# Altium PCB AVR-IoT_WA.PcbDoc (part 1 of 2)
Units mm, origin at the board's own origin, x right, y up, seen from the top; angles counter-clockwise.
Board outline 63.5 x 25.4 mm, 4 copper layers (Top-Layer, Ground Plane, Power Plane, Bottom Layer), stack 1.594 mm thick; 81 components, 91 nets, 345 pads, 206 vias.
Unrouted connection lines stored in the file: 10.
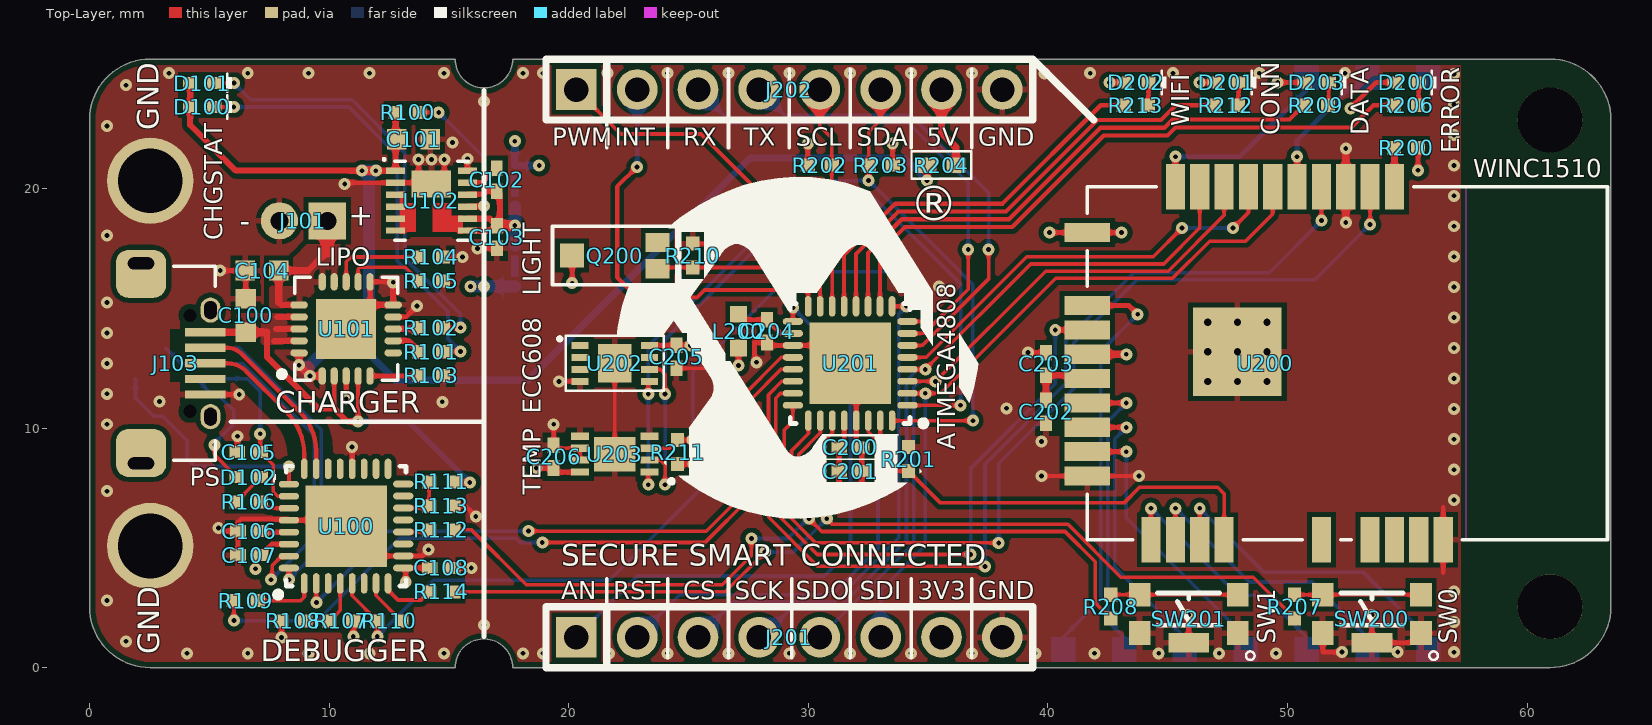
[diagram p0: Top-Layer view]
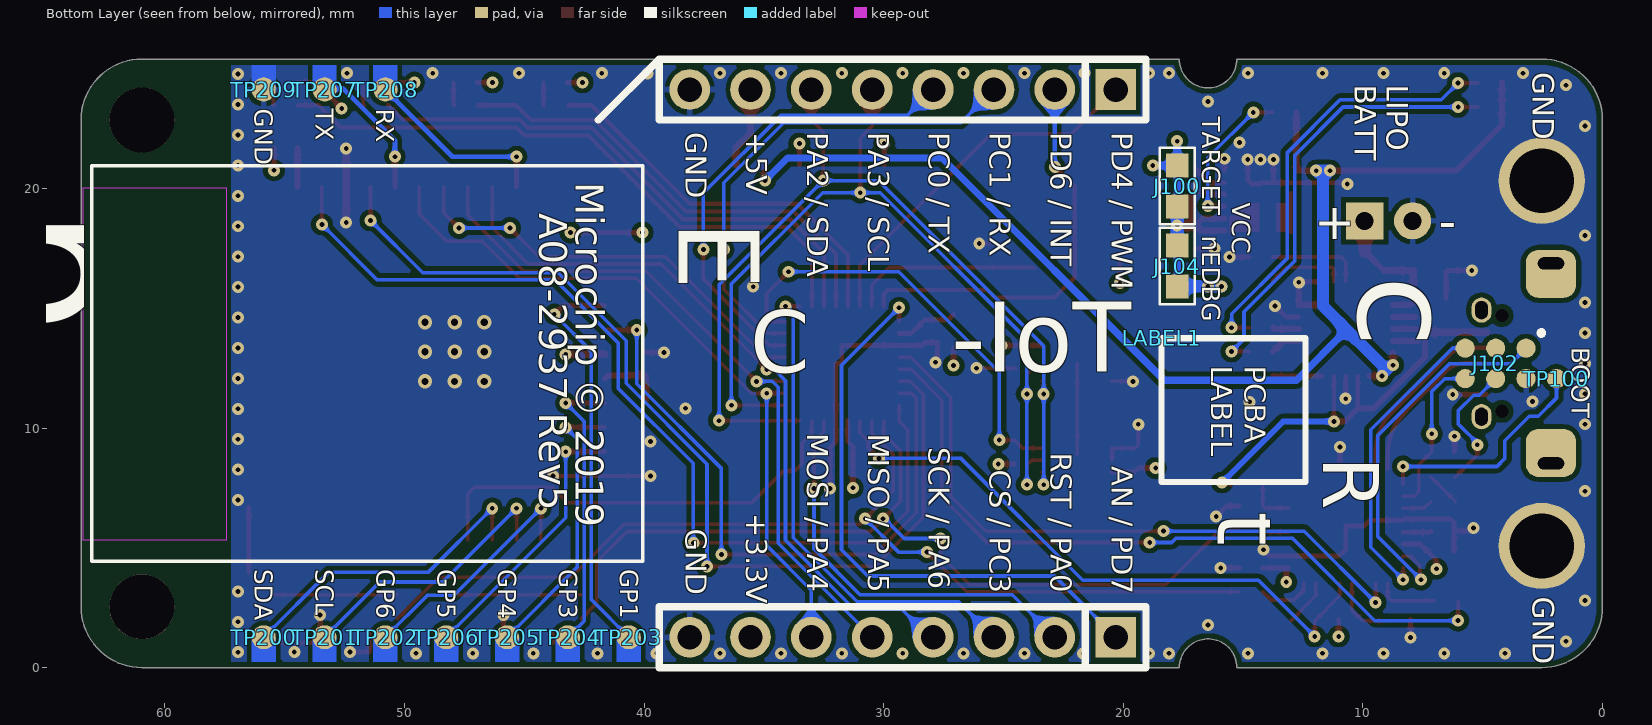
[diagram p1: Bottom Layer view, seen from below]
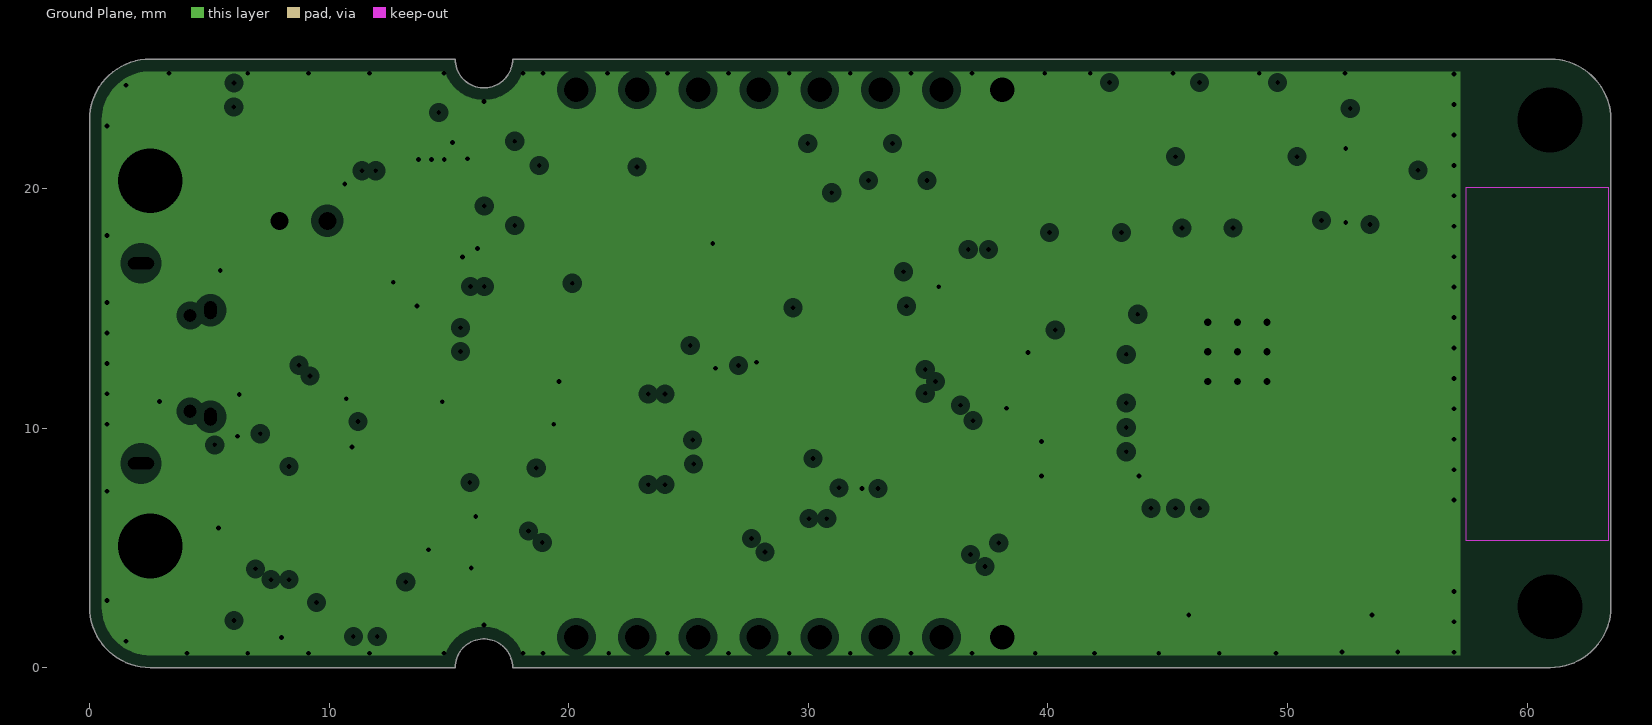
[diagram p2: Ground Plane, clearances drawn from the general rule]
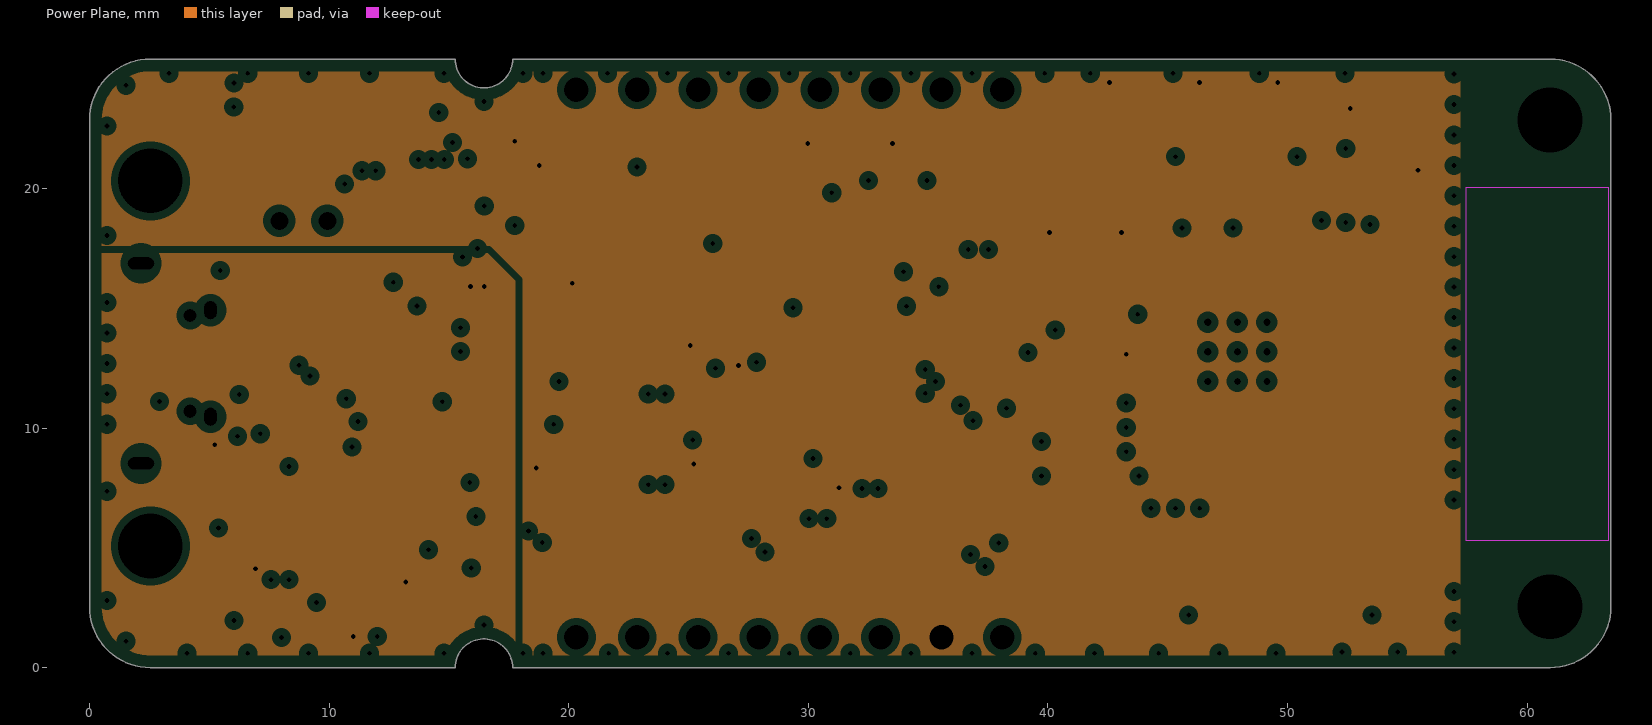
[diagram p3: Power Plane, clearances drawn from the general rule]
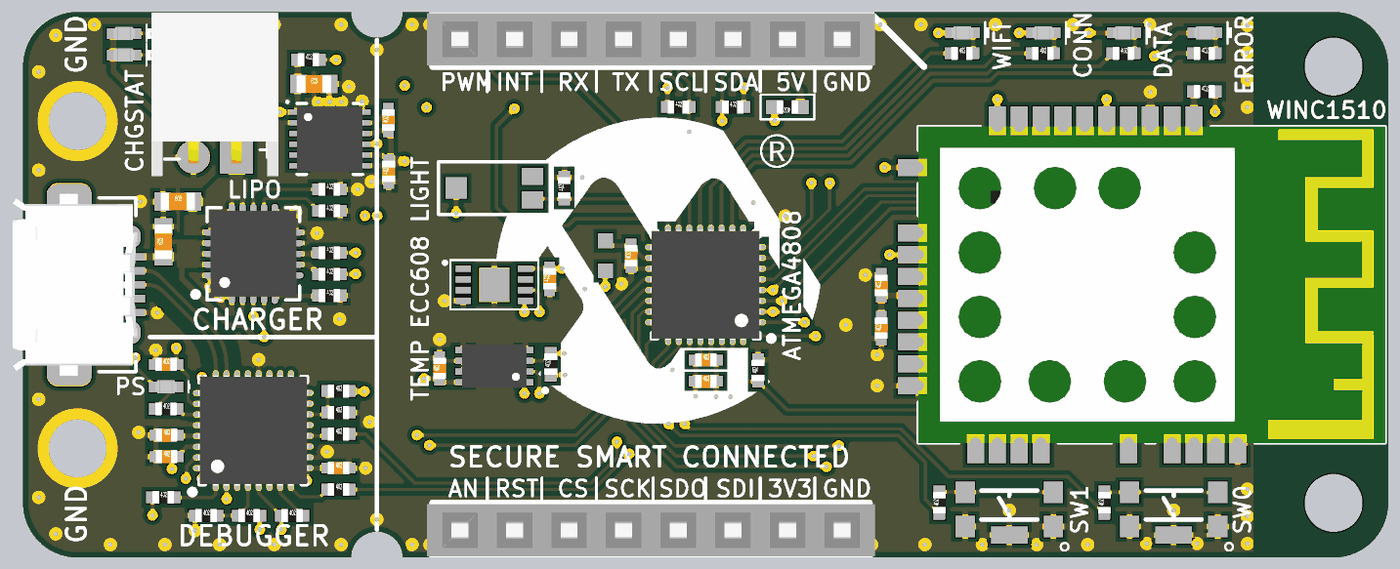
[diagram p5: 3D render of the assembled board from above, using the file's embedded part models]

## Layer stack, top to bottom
Top Solder: solder mask 0.0102, Solder Resist, Dk 3.5
Top-Layer: signal copper 0.035
Dielectric 1: prepreg 0.127, FR-4, Dk 4.2
Ground Plane: plane copper 0.035, net GND
Dielectric 3: core 1.2, Dk 4.2
Power Plane: plane copper 0.035, net (Multiple Nets)
Dielectric 4: prepreg 0.127, Dk 4.2
Bottom Layer: signal copper 0.035
Bottom Solder: solder mask 0.0102, Solder Resist, Dk 3.5

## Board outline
0,2.54 0,22.86 cw(c2.54,22.86) 2.54,25.4 15.26,25.4 ccw(c16.46,25.4) 17.66,25.4 60.96,25.4 cw(c60.96,22.86) 63.5,22.86 63.5,2.54 cw(c60.96,2.54) 60.96,0 17.66,0 ccw(c16.46,0) 15.26,0 2.54,0 cw(c2.54,2.54)

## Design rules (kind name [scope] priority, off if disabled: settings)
AcuteAngle [All] p1: minimum=8.00000000000000E+0001 checktracksonly=TRUE
AssemblyTestPointUsage [All] p1: valid=2 allowmultiple=TRUE
AssemblyTestpoint AssemblyTestpoint_1 [OnBottomLayer and IsComponent] p1: testpointundercomponent=TRUE minsize=0.8 maxsize=10 preferedsize=0.8 minholesize=0 maxholesize=5 preferedholesize=0.25 testpointgrid=0.025 usegrid=FALSE gridtolerance=0 allowsidebottom=TRUE minspacing=1.27 compbodyclearance=1.27
AssemblyTestpoint [All] p2: testpointundercomponent=TRUE minsize=0.8 maxsize=10 preferedsize=0.8 minholesize=0 maxholesize=5 preferedholesize=0.25 testpointgrid=0.025 usegrid=FALSE gridtolerance=0 allowsidebottom=TRUE minspacing=1.27
BoardOutlineClearance BoardOutlineClearance_SilkTracks [IsTrack AND (OnTopSilkscreen OR OnBottomSilkscreen)] p1: gap=0 ignorepadtopadclearanceinfootprint=FALSE
BoardOutlineClearance [All] p2: gap=0.25 ignorepadtopadclearanceinfootprint=FALSE
Clearance Clearance_Via_in_Pad [IsVia AND InNet('GND')] p1: gap=0 ignorepadtopadclearanceinfootprint=FALSE
Clearance Clearance_Poly_Impedance [IsRegion vs InDifferentialPairClass('All Differential Pairs')] p2: gap=0.6 ignorepadtopadclearanceinfootprint=FALSE except(0: Arc-Hole Track-Hole SMDPad-Hole THPad-Hole Via-Hole Fill-Hole Poly-Hole Region-Hole Text-Hole)
Clearance Clearance_Poly [InPoly] p3: gap=0.2 ignorepadtopadclearanceinfootprint=FALSE
Clearance Clearance_same_net [All] p4: gap=0 ignorepadtopadclearanceinfootprint=FALSE
Clearance [All] p5: gap=0.15 ignorepadtopadclearanceinfootprint=FALSE
ComponentClearance ComponentClearance_BETWEEN_TESTPOINTS [InComponentClass('Testpoints') or HasFootprint('AP8-01149') vs InComponentClass('Testpoints') or HasFootprint('AP8-01149')] p1: gap=0 collisioncheckmode=3 verticalgap=0 showdistances=FALSE
ComponentClearance ComponentClearance_BOOT [InComponent('TP100') vs InComponent('J102')] p2: gap=0 collisioncheckmode=3 verticalgap=0 showdistances=FALSE
ComponentClearance ComponentClearance_LABEL [InComponent('LABEL1')] p3: gap=0 collisioncheckmode=3 verticalgap=0 showdistances=FALSE
ComponentClearance [All] p4: gap=0.254 collisioncheckmode=3 verticalgap=0.254 showdistances=TRUE
DiffPairsRouting [All] p1: maxlimit=0.22 minlimit=0.2 mostfreqgap=0.2 toplayer_minwidth=0.18 toplayer_maxwidth=0.18 toplayer_prefwidth=0.18 bottomlayer_minwidth=0.18 bottomlayer_maxwidth=0.18 bottomlayer_prefwidth=0.18 maxuncoupledlength=20
FabricationTestPointUsage TestPointUsage [All] p1: valid=2 allowmultiple=TRUE
FabricationTestpoint Testpoint [All] p1: side=2 testpointundercomponent=TRUE minsize=0.55 maxsize=10 preferedsize=0.8 minholesize=0 maxholesize=5 preferedholesize=0.25 testpointgrid=0 allowsidebottom=TRUE usegrid=FALSE gridtolerance=0 minspacing=1.27
HoleSize [All] p1: absolutevalues=TRUE maxlimit=10 minlimit=0.2 maxpercent=80.000 minpercent=20.000
HoleToHoleClearance HoleToHoleClearance_NPTH [(HoleDiameter > 0) And (PadIsPlated = 'False')] p1: gap=0.25 allowstackedmicrovias=TRUE
HoleToHoleClearance [All] p2: gap=0.3 allowstackedmicrovias=TRUE
MinimumAnnularRing [All] p1: minimumring=0.15
MinimumSolderMaskSliver [All] p1: minsoldermaskwidth=0.08
NetAntennae [Not IsTestpoint] p1: netantennaetolerance=0
PlaneClearance [All] p1: clearance=0.3
PlaneConnect PlaneConnect_VIA [IsVia OR HasPad('Free-666') OR HasPad('Free-EDGE')] p1: planeconnectstyle=Direct reliefexpansion=0.508 reliefentries=4 reliefconductorwidth=0.254 reliefairgap=0.254
PlaneConnect [All] p2: planeconnectstyle=Relief reliefexpansion=0.508 reliefentries=4 reliefconductorwidth=0.254 reliefairgap=0.254
PolygonConnect PolygonConnect_VIA [IsVia OR HasPad('Free-666') OR HasFootprint('AP8-00870')] p1: connectstyle=Direct reliefconductorwidth=0.254 reliefentries=4 polygonreliefangle="90 Angle" airgapwidth=0.254
PolygonConnect [All] p2: connectstyle=Relief reliefconductorwidth=0.254 reliefentries=4 polygonreliefangle="90 Angle" airgapwidth=0.2
RoutingVias [All] p1: holewidth=0.25 width=0.55 viastyle="Through Hole" minholewidth=0.2 minwidth=0.5 maxholewidth=0.5 maxwidth=1
SMDNeckDown [All] p1: percent=98.000
ShortCircuit ShortCircuit_NC_edge_connector [IsPad AND OnLayer('Multi-Layer') AND HasFootprint('AP8-01100') vs IsPad AND OnLayer('Multi-Layer') AND HasFootprint('AP8-01100')] p1: allowed=TRUE
ShortCircuit [All] p2: allowed=FALSE
SilkToSilkClearance SilkToSilkClearance_Text [IsText] p1: silktosilkclearance=0
SilkToSilkClearance [All] p2: silktosilkclearance=0.1
SilkToSolderMaskClearance SilkscreenOverComponentPads_Soldermask [All] p1: minsilkscreentomaskgap=0.12 clearancetoexposedcopper=FALSE
SilkToSolderMaskClearance SilkscreenOverComponentPads_Copper [All] p2: minsilkscreentomaskgap=0.2 clearancetoexposedcopper=TRUE
SolderMaskExpansion SolderMaskTenting [IsVia AND NOT (IsFabTestpoint OR IsAssyTestpoint OR InAnyComponent)] p1: expansion=-1 istentingtop=FALSE
SolderMaskExpansion [All] p2: expansion=0.06 istentingtop=FALSE
ViasUnderSMD ViasUnderSMD_GND [InPadClass('Ground_Pads')] p1: allowed=TRUE
ViasUnderSMD ViasUnderSMD_Testpoint [InNet('BOOT') or InNet('GND')] p2: allowed=TRUE
ViasUnderSMD [All] p3: allowed=FALSE
Width Width_Power [InNetClass('Power')] p1: maxlimit=0.5 minlimit=0.175 preferedwidth=0.25
Width [All] p2: maxlimit=10 minlimit=0.15 preferedwidth=0.15
15 further rules are at their usual default settings.

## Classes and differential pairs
component class AVR-IoT_WA_TopLevel: FW1 LABEL1 PCB1 PCBADOC1 TEST1 TESTDOC1
component class S2: C200 C201 C202 C203 C204 C205 C206 D200 D201 D202 D203 J201 J202 L200 Q200 R200 R201 R202 R203 R204 R206 R207 R208 R209 R210 R211 R212 R213 SW200 SW201 TP200 TP201 TP202 TP203 TP204 TP205 TP206 TP207 TP208 TP209 U200 U201 U202 U203
component class S1: C100 C101 C102 C103 C104 C105 C106 C107 C108 D100 D101 D102 J100 J101 J102 J103 J104 R100 R101 R102 R103 R104 R105 R106 R107 R108 R109 R110 R111 R112 R113 R114 TP100 U100 U101 U102
differential pair USBD: +USBD_P -USBD_N

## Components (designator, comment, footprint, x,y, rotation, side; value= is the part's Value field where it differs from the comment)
C100 "" AP1-00117 6.526,14.7 r90 top locked value=4.7uF
C101 "" AP1-00117 13.526,22.05 r0 top locked value=4.7uF
C102 "" AP1-00053 16.998,20.366 r90 top locked value=560p
C103 "" AP1-00053 17.004,17.975 r90 top locked value=10uF
C104 "" AP1-00117 7.2,16.575 r0 top locked value=4.7uF
C105 "" AP1-00053 6.65,8.995 r0 top locked value=100n
C106 "" AP1-00053 6.672,5.7 r0 top locked value=1u
C107 "" AP1-00053 6.672,4.698 r0 top locked value=100n
C108 "" AP1-00053 14.675,4.164 r0 top locked value=100n
C200 "" AP1-00053 31.763,9.198 r0 top locked value=100n
C201 "" AP1-00053 31.763,8.203 r0 top locked value=2.2uF
C202 "" AP1-00053 39.923,10.681 r90 top locked value=10nF
C203 "" AP1-00053 39.923,12.675 r90 top locked value=10uF
C204 "" AP1-00053 28.285,14.048 r90 top locked value=100n
C205 "" AP1-00053 24.498,12.975 r90 top locked value=100n
C206 "" AP1-00053 19.375,8.808 r90 top locked value=100n
D100 "" AP4-00160 4.7,23.402 r180 top locked value="GREEN LED"
D101 "" AP4-00160 4.7,24.402 r180 top locked value="RED LED"
D102 "" AP4-00160 6.65,7.95 r180 top locked value="GREEN LED"
D200 "" AP4-00160 54.975,24.425 r180 top locked value="RED LED"
D201 "" AP4-00160 47.458,24.425 r180 top locked value="GREEN LED"
D202 "" AP4-00160 43.7,24.425 r180 top locked value="BLUE LED"
D203 "" AP4-00160 51.217,24.425 r180 top locked value="YELLOW LED"
J100 "" AP9-00044 17.75,20.104 r270 bottom locked net-tie value=SMD-STRAP_0603_CLOSED
J101 "" AP8-00831 8.925,18.65 r0 top locked value=S2B-PH-K-S
J102 "" AP8-00997 5.73,12.7 r0 bottom locked value="Testpoint Array"
J103 "" AP8-01099 2.15,12.7 r270 top locked value=MU-MB0142AB2-269
J104 "" AP9-00044 17.75,16.763 r90 bottom locked net-tie value=SMD-STRAP_0603_CLOSED
J201 "" AP8-01081 29.21,1.27 r0 top locked value=2185-108SS0CYNP1
J202 "" AP8-01081 29.21,24.13 r0 top locked value=2185-108SS0CYNP1
L200 "" AP3-00005 27.085,14.048 r270 top locked value=BLM18PG471SN1
LABEL1 "" AP9-00049 18.4,13.75 r270 bottom value="Label PCBA Small 6x6mm"
Q200 "" AP9-00011 21.923,17.202 r180 top locked value=TEMT6000
R100 "" AP2-00011 13.275,23.175 r0 top locked value=100k
R101 "" AP2-00011 14.254,13.189 r0 top locked value=1k
R102 "" AP2-00011 14.254,14.191 r0 top locked value=1k
R103 "" AP2-00011 14.254,12.2 r0 top locked value=10k
R104 "" AP2-00011 14.254,17.141 r0 top locked value=10k
R105 "" AP2-00011 14.254,16.139 r0 top locked value=100k
R106 "" AP2-00011 6.65,6.92 r0 top locked value=1k
R107 "" AP2-00011 10.512,1.95 r0 top locked value=100k
R108 "" AP2-00011 8.512,1.95 r0 top locked value=100k
R109 "" AP2-00011 6.525,2.8 r0 top locked value=330R
R110 "" AP2-00011 12.512,1.95 r0 top locked value=1k
R111 "" AP2-00011 14.675,7.75 r0 top locked value=100k
R112 "" AP2-00011 14.675,5.75 r0 top locked value=330R
R113 "" AP2-00011 14.675,6.75 r0 top locked value=100k
R114 "" AP2-00011 14.675,3.164 r0 top locked value=330R
R200 "" AP2-00011 54.95,21.7 r0 top locked value=100k
R201 "" AP2-00011 34.185,8.709 r90 top locked value=100k
R202 "" AP2-00011 30.48,20.975 r0 top locked value=4.7k
R203 "" AP2-00011 33.02,20.975 r0 top locked value=4.7k
R204 "" AP2-00000 35.56,20.975 r180 top locked value=0R
R206 "" AP2-00011 54.95,23.475 r0 top locked value=1k
R207 "" AP2-00011 50.3,2.55 r90 top locked value=330R
R208 "" AP2-00011 42.624,2.55 r90 top locked value=330R
R209 "" AP2-00011 51.192,23.475 r0 top locked value=1k
R210 "" AP2-00011 25.175,17.202 r90 top locked value=10k
R211 "" AP2-00011 24.548,9 r90 top locked value=100k
R212 "" AP2-00011 47.433,23.475 r0 top locked value=1k
R213 "" AP2-00011 43.675,23.475 r0 top locked value=1k
SW200 "" AP8-00274 55.575,1.443 r180 top locked value=KMR221G
SW201 "" AP8-00274 47.927,1.443 r180 top locked value=KMR221G
TP100 "PCB implemented component." AP8-00870 1.92,12.065 r270 bottom locked value="SMD Test point - 0.8mm"
TP200 "" AP8-01149 55.88,1.27 r90 bottom locked value=TESTPAD
TP201 "" AP8-01149 53.34,1.27 r90 bottom locked value=TESTPAD
TP202 "" AP8-01149 50.8,1.27 r90 bottom locked value=TESTPAD
TP203 "" AP8-01149 40.64,1.27 r90 bottom locked value=TESTPAD
TP204 "" AP8-01149 43.18,1.27 r90 bottom locked value=TESTPAD
TP205 "" AP8-01149 45.72,1.27 r90 bottom locked value=TESTPAD
TP206 "" AP8-01149 48.26,1.27 r90 bottom locked value=TESTPAD
TP207 "" AP8-01149 53.34,24.13 r90 bottom locked value=TESTPAD
TP208 "" AP8-01149 50.8,24.13 r90 bottom locked value=TESTPAD
TP209 "" AP8-01149 55.88,24.13 r90 bottom locked value=TESTPAD
U100 "QFN32" AP6-00418 10.708,5.91 r0 top locked value=SAMD21E18A-MUT
U101 "" AP6-00165 10.712,14.139 r90 top locked value=MCP73871
U102 "" AP6-00528 14.273,19.491 r0 top locked value=MIC33050-SYHL
U200 "Firmware version 19.6.1" AP9-00127 52.5,12.7 r0 top locked value=ATWINC1510-MR210PB1961
U201 "" AP6-00418 31.75,12.696 r90 top locked value=ATmega4808-MFR
U202 "" AP6-00409 21.923,12.7 r0 top locked value="ATECC608A I2C (Google Cloud)"
U203 "" AP6-00519 21.923,8.912 r180 top value=MCP9808

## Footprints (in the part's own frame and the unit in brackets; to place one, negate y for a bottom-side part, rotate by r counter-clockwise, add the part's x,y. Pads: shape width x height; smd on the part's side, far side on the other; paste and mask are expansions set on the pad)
AP1-00053 [mm] "Chip Capacitor, 2-Leads, Body 1.0x0.5mm, IPC High Density"
  rect 0.65x0.5 smd: 1(-0.475,0) 2(0.475,0)
  body extent -0.5,-0.3 0.5,0.3, height 0.2
AP1-00117 [mm] "Chip Capacitor, 2-Leads, Body 1,60x0,80mm, IPC High Density"
  rect 0.8x0.85 smd: 1(-0.7,0) 2(0.7,0)
  body extent -0.8,-0.4 0.8,0.4, height 0.3
AP2-00000 [mm] "Standard 0402 SMD resistor footprint"
  rect 0.8x0.65 smd: 1(-0.6,0) 2(0.6,0)
  silkscreen extent -1.25,-0.58 1.25,0.58, body extent -0.5,-0.3 0.5,0.3, height 0.2
AP2-00011 [mm] "Chip Resistor, 2-Leads, Body 1,0x0,5mm, IPC High Density"
  rect 0.6x0.55 smd: 1(-0.5,0) 2(0.5,0)
  body extent -0.5,-0.3 0.5,0.3, height 0.2
AP3-00005 [mm]
  rect 0.7x0.7 smd: 1(-0.7,0) 2(0.7,0)
  body extent -0.83,-0.41 0.82,0.41, height 0.8
AP4-00160 [mm] "ROHM SML-P11 0402 LED"
  rect 0.6x0.5 smd: 1(-0.5,0) 2(0.5,0)
  silkscreen extent -1.25,-0.5 -1.05,0.5, body extent -0.5,-0.3 0.5,0.3, height 0.19
AP6-00165 [mm] "QFN, 20-Leads, Body 4,00x4,00mm, Pitch 0,50mm, Thermal Pad 2,70x2,70mm, IPC High Density"
  oval 0.73x0.3 smd: 1(-1.965,1) 2(-1.965,0.5) 3(-1.965,0) 4(-1.965,-0.5) 5(-1.965,-1) 11(1.965,-1) 12(1.965,-0.5) 13(1.965,0) 14(1.965,0.5) 15(1.965,1)
  oval 0.3x0.73 smd: 6(-1,-1.965) 7(-0.5,-1.965) 8(0,-1.965) 9(0.5,-1.965) 10(1,-1.965) 16(1,1.965) 17(0.5,1.965) 18(0,1.965) 19(-0.5,1.965) 20(-1,1.965)
  rect 2.5x2.5 smd: 21(0,0)
  silkscreen extent -2.15,-2.15 2.15,2.81, body extent -2,-2 2,2, height 0.9
AP6-00409 [mm]
  rect 0.7x0.3 smd mask-1: 1(-1.45,0.75) 2(-1.45,0.25) 3(-1.45,-0.25) 4(-1.45,-0.75) 5(1.45,-0.75) 6(1.45,-0.25) 7(1.45,0.25) 8(1.45,0.75)
  rect 1.4x1.6 smd paste-0.025 mask+0.075: 9(0,0)
  silkscreen extent -2.37,-1.15 2.05,1.15, body extent -1.55,-1.05 1.55,1.05, height 0.6
AP6-00418 [mm] "MLF-32 solder foot print"
  oval 0.28x0.85 smd paste-0.03 mask+0: 1(-1.746,-2.39) 2(-1.246,-2.39) 3(-0.746,-2.39) 4(-0.246,-2.39) 5(0.254,-2.39) 6(0.754,-2.39) 7(1.254,-2.39) 8(1.754,-2.39) 17(1.754,2.39) 18(1.254,2.39) 19(0.754,2.39) 20(0.254,2.39) 21(-0.246,2.39) 22(-0.746,2.39) 23(-1.246,2.39) 24(-1.746,2.39)
  oval 0.85x0.28 smd paste-0.03 mask+0: 9(2.386,-1.746) 10(2.386,-1.246) 11(2.386,-0.746) 12(2.386,-0.246) 13(2.386,0.254) 14(2.386,0.754) 15(2.386,1.254) 16(2.386,1.754) 25(-2.383,1.746) 26(-2.383,1.246) 27(-2.383,0.746) 28(-2.383,0.246) 29(-2.383,-0.254) 30(-2.383,-0.754) 31(-2.383,-1.254) 32(-2.386,-1.75)
  rect 3.4x3.4 smd paste-1.7 mask+0: 33(0.004,0)
  silkscreen extent -2.96,-2.98 2.5,2.5, body extent -2.55,-2.55 2.55,2.55, height 1
AP6-00519 [mm] "DFN 2mm x 3mm, 0.9mm height"
  round 0.264 on Top Paste: 0(-0.425,0.4) 0(-0.425,-0.4) 0(0,0) 0(0.425,0.4) 0(0.425,-0.4)
  rect 0.75x0.3 smd: 1(-1.45,0.75) 2(-1.45,0.25) 3(-1.45,-0.25) 4(-1.45,-0.75) 5(1.45,-0.75) 6(1.45,-0.25) 7(1.45,0.25) 8(1.45,0.75)
  rect 1.75x1.45 smd paste-0.7: 9(0,0)
  silkscreen extent -2.42,1.08 -2.31,1.19, body extent -1.5,-1 1.5,1, height 1
AP6-00528 [mm] "MLF, 12-Leads, Body 3,00x3,00mm, Pitch 0,50mm, IPC High Density"
  rect 0.8x0.26 smd: 1(-1.5,1.25) 2(-1.5,0.75) 3(-1.5,0.25) 4(-1.5,-0.25) 5(-1.5,-0.75) 6(-1.5,-1.25) 7(1.5,-1.25) 8(1.5,-0.75) 9(1.5,-0.25) 10(1.5,0.25) 11(1.5,0.75) 12(1.5,1.25)
  rect 1.65x1.125 smd paste-0.2: 13(0,0.7)
  Top-Layer region: -1.325,0.375 -1.125,0.375 -1.125,-0.1 -0.65,-0.1 -0.65,-1.3 -0.988,-1.3 -1.1,-1.375 -1.325,-1.375
  Top-Layer region: 1.3,-0.625 1.3,-1.375 1.1,-1.375 1.025,-1.3 0.05,-1.3 0.05,-0.1 0.825,-0.1 0.825,-0.625
  silkscreen extent -2.02,-1.65 1.52,1.77, body extent -1.53,-1.53 1.53,1.53, height 0.9
AP8-00274 [mm] "SMD 4.6X2.8 push button. KMR221G"
  rect 0.9x1 smd: 1(0,0) 2(0,-1.6) 3(4.1,0) 4(4.1,-1.6)
  rect 1.7x0.8 smd: 5(2.05,0.4)
  silkscreen extent -0.7,-1.68 3.35,1.12, body extent -0.25,-2.2 4.35,0.6, height 1.9
AP8-00831 [mm] "JP_1x2, rigth entry"
  round 1.524 on Top Paste: 0(-1,0)
  rect 1.55x1.55 on Top Paste: 0(1,0)
  rect 1.55x1.55 hole 0.75: 1(1,0)
  round 1.55 hole 0.75: 2(-1,0)
  body extent -2.95,-0.89 2.95,6.71, height 4.8
AP8-00870 [mil] "TP_SMT_.8mm"
  round 31.5 smd paste-39.37: 1(0,0)
AP8-00997 [mm] "SMT test point array 2x5 0.8mm, Pitch 1.27 mm"
  round 0.8 smd paste-1: 1(-2.54,-0.635) 2(-2.54,0.635) 3(-1.27,-0.635) 4(-1.27,0.635) 5(0,-0.635) 6(0,0.635)
  silkscreen extent -3.28,-1.37 -3.07,-1.17
AP8-01081 [mm] "1 x 8 pin female pin header, 2.54mm, PIP, Pick plate"
  rect 2.1x2.1 on Top Paste: 0(-8.89,0) 0(-6.35,0) 0(-3.81,0) 0(-1.27,0) 0(1.27,0) 0(3.81,0) 0(6.35,0) 0(8.89,0)
  rect 1.7x1.7 hole 1.02: 1(-8.89,0)
  round 1.7 hole 1.02: 2(-6.35,0) 3(-3.81,0) 4(-1.27,0) 5(1.27,0) 6(3.81,0) 7(6.35,0) 8(8.89,0)
  body extent -10.41,-1.21 10.41,1.21, height 8.51
AP8-01099 [mm] "Micro USB AB connector from Allen Creations. Signals surface mount, shield DIP"
  rrect52% 2x2.1 on Top Paste: 0(-3.69,0) 0(3.69,0)
  rrect100% 1.05x0.84 on Top Paste: 0(-2.225,2.9) 0(2.225,2.9)
  rect 0.35x1.7 smd: 1(-1.3,2.68) 2(-0.65,2.68) 3(0,2.68) 4(0.65,2.68) 5(1.3,2.68)
  rrect52% 2x2.1 hole 0.5 slot 1.1 at 90 deg copper offset 0.437,0: 6(-4.175,0)
  rrect52% 2x2.1 hole 0.5 slot 1.1 at 90 deg copper offset -0.437,0: 7(4.175,0)
  rrect100% 1.05x0.84 hole 0.54 slot 0.75 at 0 deg: 8(-2.225,2.9) 9(2.225,2.9)
  round 0 hole 0.55 unplated: 10(-2,2.05) 11(2,2.05)
  silkscreen extent -4.05,1.38 4.05,3.1, body extent -4.32,-2.65 4.33,3.25, height 2.78
AP8-01149 [mm] "Single Testpad, 1mm"
  round 1 smd paste-1: 1(0,0)
AP9-00011 [mm]
  rect 1x1 smd: 1(1.775,0)
  rect 1x0.8 smd: 2(-1.775,0.55) 3(-1.775,-0.55)
  silkscreen extent -2.6,-1.23 2.6,1.22, body extent -2.3,-1 2.28,1, height 1.05
AP9-00044 [mm]
  rect 1x0.95 smd paste-1: 1(-0.85,0) 2(0.85,0)
  Top-Layer region: -0.45,0.15 0.45,0.15 0.45,-0.15 -0.45,-0.15
  silkscreen extent -1.6,-0.72 1.6,0.72, body extent -0.8,-0.4 0.8,0.4, height 0.3
AP9-00049 [mm] "Placement area for 6x6mm sticker"
  silkscreen extent 0,0 6,6
AP9-00127 [mm]
  rect 0.8x1.9 smd: 1(-8.191,-7.366) 2(-7.175,-7.366) 3(-6.159,-7.366) 4(-5.143,-7.366) 5(-1.079,-7.366) 6(0.953,-7.366) 7(1.968,-7.366) 8(2.984,-7.366) 9(4,-7.366) 10(1.968,7.366) 11(0.953,7.366) 12(-0.064,7.366) 13(-1.079,7.366) 14(-2.095,7.366) 15(-3.111,7.366) 16(-4.127,7.366) 17(-5.143,7.366) 18(-6.159,7.366) 19(-7.175,7.366)
  rect 1.9x0.8 smd: 20(-10.858,5.461) 21(-10.858,2.413) 22(-10.858,1.397) 23(-10.858,0.381) 24(-10.858,-0.635) 25(-10.858,-1.651) 26(-10.858,-2.667) 27(-10.858,-3.683) 28(-10.858,-4.699)
  rect 3.7x3.7 smd: 29(-4.588,0.484)
  Keep-Out Layer region: 4.94,-7.391 10.909,-7.391 10.909,7.341 4.94,7.341
  silkscreen extent -10.86,-7.37 10.86,7.37, body extent -10.86,-7.37 10.86,7.37, height 1.96

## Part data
C100 C101 C104: library part A01-0377, "Ceramic capacitor, SMD 0603, X5R, 10V, 10% (de31036)", Manufacturer="WALSIN Technology Corporation", MPN=0603X475K100CT, TemperatureRange="-55 - +85 deg C", Tolerance=10%
C102: library part A01-0035, "Ceramic capacitor, SMD 0402, X7R, 50V, +/-10%", TemperatureRange="-55 - +125 deg C", Tolerance="50V, +/-10%"
C103 C203: library part A01-0778, "Ceramic capacitor, SMD 0402, X5R, 6.3V, 20%", Manufacturer=Murata, MPN=GRM155R60J106ME15, TemperatureRange="-55 to 85 Deg.C", Tolerance=+/-20%
C105 C107 C108 C200 C204 C205 C206: library part A01-0246, "Ceramic capacitor, SMD 0402, X7R, 16V, +/-10%", Manufacturer=Kemet, MPN=C0402C104K4RACTU, TemperatureRange="-55 - +125 deg C", Tolerance="16V, +/-10%"
C106: library part A01-0286, "Ceramic capacitor, SMD 0402, X5R, 6.3V, +/-10% (de26942)", Manufacturer=Kemet, MPN=C0402C105K9PAC, TemperatureRange="-55 to 85 deg C", Tolerance=+/-10%
C201: library part A01-0493, "CAP CER 2.2UF 10V 10% X5R 0402", Manufacturer=tdk, MPN=C1005X5R1A225K, TemperatureRange="-55 to 85C", Tolerance=+/-10%
C202: library part A01-0636, "Ceramic capacitor, SMD 0402, X7R, 25V, 10%", Manufacturer=Murata, MPN=GRM155R71E103KA01D, TemperatureRange="-55 to +125deg C", Tolerance=10%
D100 D102 D201: library part A10-0213, "LED, SMD 0402, Green, Wave length=569nm, 2.1mcd @ (1mA, 1.9Vf)rohm", Manufacturer=ROHM, MPN=SML-P12MTT86R, TemperatureRange="-40 to +85"
D101 D200: library part A10-0220, "LED, SMD 0402, Red, Wave length=630nm, 2.1mcd @ (1mA, 1.7Vf)rohm", Manufacturer=ROHM, MPN=SML-P12VTT86R, TemperatureRange="-40 to +85"
D202: library part A10-0219, "LED, SMD 0402, Blue, Wave length=470nm, 25mcd @ (5mA, 2.9Vf)rohm", Manufacturer=ROHM, MPN=SMLP13BC8TT86, TemperatureRange="-40Â°C to +85Â°C"
D203: library part A10-0215, "LED, SMD 0402, Yellow, Wave length=586nm, 7.6mcd @ (1mA, 1.9Vf)", Manufacturer=ROHM, MPN=SML-P12YTT86R, TemperatureRange="-40 to +85"
J100 J104: library part A09-0783, "Default closed SMD strap, 0603 size"
J101: library part A08-2071, "Pin Header 1x2, 2mm THM, right entry, 100V AC/DC, 2A AC/DC (AWG #24)  (Element14:9491902)", Manufacturer="J.S.T. Mfg. Co. Ltd.", MPN=S2B-PH-K-S, TemperatureRange="-25Â°C to +85Â°C"
J102: library part A08-2568, "10-pin Testpoint Array, 0.8mm Pad, 1.27mm Pitch"
J103: library part A08-2839, "USB micro AB, Surface mount signals and DIP shield", Manufacturer="Allen Creations Corp.", MPN=MU-MB0142AB2-269, TemperatureRange="-30Â°C to +80Â°C"
J201 J202: library part A08-2791, "1x8 receptacle pin header, 2.54mm pitch THM, PIP", Manufacturer=WCON, MPN=2185-108SS0CYNP1
L200: library part A03-0035, "SMD RF inductor 0603. Z=470Ohm (@100MHz), Max R(dc)=0.20Ohm, Max current=1A", Manufacturer=Murata, MPN=BLM18PG471SN1, TemperatureRange=-55
LABEL1: library part A09-0612, "PCBA identification label PP Top White Gloss", Manufacturer="ACT Logimark AS", MPN=505462
Q200: library part A10-0025, "light sensor", Manufacturer=vishay, MPN=TEMT6000X01
R100 R105 R107 R108 R111 R113 R200 R201 R211: library part A02-0260, "Thick film resistor, SMD 0402, 1/16W, 1%", Manufacturer="ASJ Holdings", MPN=CR10-1003-FK, TemperatureRange="-55ï¿½ to +125ï¿½C", Tolerance="1 %"
R101 R102 R106 R110 R206 R209 R212 R213: library part A02-0212, "Thick film resistor, SMD 0402, 1/16W, 1%", Manufacturer="ASJ Holdings", MPN=CR10-1001-FK, TemperatureRange="-55 - +125 deg C", Tolerance="1 %"
R103 R104 R210: library part A02-0835, "Thick film resistror, SMD 0402, 1/16W, 1%", Manufacturer=Yageo, MPN=RC0402FR-0710KL, TemperatureRange="â€“55 to +155 deg C", Tolerance=1%
R109 R112 R114 R207 R208: library part A02-0882, "Thick film resistor, SMD 0402, 1/16W, 1%", Manufacturer=Yageo, MPN=RC0402FR-07330RL, TemperatureRange="-55 to +155 deg C", Tolerance=1%
R202 R203: library part A02-1016, "Thick film resistror, SMD 0402, 1/16W, 1%", Manufacturer=Yageo, MPN=RC0402FR-074K7L, TemperatureRange="-55 to +155 deg C", Tolerance=1%
R204: library part A02-0163, "RES 0.0 OHM 1/16W 0402 SMD", Manufacturer=(n/a), MPN=RMCF0402ZT0R00, TemperatureRange="-55 - +125 deg C", Tolerance="1 %"
SW200 SW201: library part A08-0420, "Microminiature Tact Switch for SMT", Manufacturer="ITT Corporation", MPN=KMR221G
TP100: library part A08-2176, "SMD Test point - 0.8mm"
TP200 TP201 TP202 TP203 TP204 TP205 TP206 TP207 TP208 TP209: library part A08-2933, "SMD Single Testpad, 1mm, No-silk"
U100: library part A06-1205, "32-bit RISC MCU 32pin", Manufacturer=Microchip, MPN=ATSAMD21E18A-MUT, TemperatureRange="-40Â°C to +85Â°C"
U101: library part A06-1643, "Load Sharing and Li-Ion/Li-Polymer Battery Charge Management Controller", Manufacturer=Microchip, MPN=MCP73871T-2CCI/ML, TemperatureRange="-40Â°C to  +85Â°C"
U102: library part A06-1644, "3.3V Fixed, 4MHz, 600mA, Buck regulator with internal inductor with HyperLight Load", Manufacturer=Microchip, MPN=MIC33050-SYHL-TR, TemperatureRange="-40C to +125C"
U200: library part A06-1660, "IEEE 802.11 b/g/n module, 8Mbit Flash Memory, with FEM, PCB Antenna, with Shield, with MAC, Firmware version 19.6.1", Manufacturer=Microchip, MPN=ATWINC1510-MR210PB1961, TemperatureRange="-40Â°C to +85Â°C"
U201: library part A06-1639, "Atmel 8-bit RISC MCU, 48K Flash, 32pin QFN", Manufacturer=Microchip, MPN=ATmega4808-MFR, TemperatureRange="-40Â°C to +125Â°C"
U202: library part A06-1647, "ATECC608A with an I2C Interface and a 8 Pin UDFN", Manufacturer=Microchip, MPN=ATECC608A-MAH1H-S
U203: library part A06-1645, "Â±0.5Â°C Maximum Accuracy Digital Temperature Sensor, I2C/SMBus", Manufacturer=Microchip, MPN=MCP9808T-E/MC, TemperatureRange="-40Â°C to +125Â°C"

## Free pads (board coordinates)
  round 3.6 hole 2.7 paste-2.6: 666(2.54,5.08) 666(2.54,20.32)
  round 2.7 hole 2.7 unplated paste-2.6: 666(60.96,2.54) 666(60.96,22.86)

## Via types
v1: diameter 0.5, hole 0.2, Top-Layer to Bottom Layer, 197 vias
v2: diameter 0.6, hole 0.3, Top-Layer to Bottom Layer, 9 vias

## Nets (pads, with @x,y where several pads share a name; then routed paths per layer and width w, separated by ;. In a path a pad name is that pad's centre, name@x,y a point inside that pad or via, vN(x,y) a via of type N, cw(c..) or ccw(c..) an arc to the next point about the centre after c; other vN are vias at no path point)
+5V: J202.7 R204.1 | length 3.4
  Top-Layer w0.3: J202.7@35.56,24.13 35.56,22.319 36.16,21.719 R204.1@36.16,20.975
BOOT: TP100.1 U100.25 | length 9.6
  Top-Layer w0.15: U100.25@8.325,7.656 v1(8.325,8.397)
  Bottom Layer w0.15: TP100.1@1.92,12.065 1.92,11.255 2.683,10.492 3.058,10.492 4.075,9.475 4.075,8.729 4.407,8.397 v1(8.325,8.397)
CDC_RX_CTRL: U100.19
CDC_TX_CTRL: U100.21
CONN: D201.1 R212.2 | length 1
  Top-Layer w0.175: R212.2@47.958,23.5 D201.1@47.958,24.425
  Top-Layer w0.2: R212.2@47.933,23.475 R212.2@47.958,23.5
DAC: U100.3
DATA: D203.1 R209.2 | length 1
  Top-Layer w0.15: R209.2@51.692,23.475 51.717,23.5 D203.1@51.717,24.425
DBG0_CTRL: U100.15
DBG1_CTRL: U100.16
DBG2_CTRL: U100.11
DBG2_GPIO: R112.1 U100.12 | length 1.1
  Top-Layer w0.15: U100.12@13.094,5.664 14.089,5.664 R112.1@14.175,5.75
DBG3_CTRL: U100.17
ERR: D200.1 R206.2 | length 1
  Top-Layer w0.175: R206.2@55.475,23.5 D200.1@55.475,24.425
  Top-Layer w0.2: R206.2@55.45,23.475 R206.2@55.475,23.5
GND: C100.2 C101.2 C103.1 C104.1 C105.1 C106.1 C107.1 C108.2 C200.2 C201.2 C202.1 C203.2 C204.1 C205.1 C206.2 J101.2 J102.2 J103.5 J201.8 J202.8 pad.666@2.54,5.08 pad.666@2.54,20.32 R103.2 R104.2 R105.2 R108.1 R113.2 R201.2 R210.2 SW200.1 SW200.3 SW200.5 SW201.1 SW201.3 SW201.5 TP209.1 U100.10 U100.20 U100.28 U100.33 U101.3 U101.9 U101.10 U101.11 U101.21 U102.2 U102.12 U102.13 U200.9 U200.12 U200.28 U200.29 U201.19 U201.29 U201.33 U202.4 U202.9 U203.4 U203.5 U203.6 U203.7 U203.9 | length 71.5
  Top-Layer w0.15: v1(19.375,10.156) C206.2@19.375,9.283 19.496,9.162 U203.6@20.473,9.162 U203.7@20.473,8.662 ; v1(19.6,11.95) U202.4@20.473,11.95 ; U203.9@21.923,8.912 U202.9@21.923,12.7 ; C205.1@24.498,12.5 v1(26.134,12.5) ; R210.2@25.175,17.702 v1(26.013,17.702) ; v1(39.731,8.001) U200.28@41.641,8.001 v1(43.801,8.001)
  Top-Layer w0.2: J103.5@4.83,11.4 v1@6.246,11.4 ; v1(5.381,5.825) v1@5.406,5.8 ; v1@5.406,5.7 C106.1@6.197,5.7 ; v1(5.456,16.575) C104.1@6.5,16.575 6.526,16.549 C100.2@6.526,15.4 ; C105.1@6.175,8.995 v1(6.175,9.659) ; C107.1@6.197,4.848 C106.1@6.197,5.7 ; v1(8.012,1.262) R108.1@8.012,2.025 ; v1(10.65,20.191) 10.7,20.241 U102.2@12.773,20.241 U102.13@13.736,20.241 ; U101.3@10.712,12.174 10.712,11.229 v1(10.717,11.225) ; U100.20@10.962,8.3 v1(10.962,9.212) ; U101.21@11.712,15.139 U101.11@11.712,16.104 v1@12.677,16.104 ; U101.9@12.677,14.639 13.214,14.639 v1(13.675,15.1) ; v1(13.736,21.216) U102.13@13.736,20.241 ; v1(14.15,4.925) 13.889,4.664 U100.10@13.094,4.664 10.986,4.664 10.712,4.938 U100.33@10.712,5.91 9.958,5.91 9.712,6.156 U100.28@8.325,6.156 8.281,6.2 6.333,6.2 6.197,6.064 C106.1@6.197,5.7 ; R104.2@14.754,17.141 v1(15.566,17.141) ; v1(14.811,21.216) 14.811,20.366 14.636,20.191 U102.13@14.273,20.191 14.273,20.241 U102.13@13.736,20.241 ; C108.2@15.15,4.164 v1(15.936,4.164) ; R113.2@15.175,6.75 15.682,6.75 v1(16.125,6.307) ; U102.12@15.773,20.741 v1(15.773,21.241) ; v1(16.2,17.5) C103.1@17.004,17.5 ; v1(27.835,12.747) 27.754,12.827 27.754,13.573 C204.1@28.285,13.573 28.408,13.45 U201.19@29.36,13.45 31.75,13.45 U201.33@31.75,12.7 32.004,12.7 U201.29@32.004,10.313 32.004,9.432 C200.2@32.238,9.198 v1(32.238,7.484) ; v1(39.175,13.15) C203.2@39.923,13.15 ; SW201.3@43.827,1.039 SW201.3@43.827,1.443 ; SW201.5@45.877,1.043 v1(45.877,2.2) ; SW200.3@51.475,1.443 51.475,0.65 v1(52.275,0.65) ; v1(53.525,2.2) SW200.5@53.525,1.043 SW200.1@55.175,1.043 ; SW200.1@55.575,1.043 SW200.1@55.975,1.443 ; 56.5,3.973 U200.9@56.5,5.334 56.5,6.695
  Top-Layer w0.25: U101.21@11.712,15.139 U101.10@12.677,15.139 12.677,15.464 ; 12.677,15.491 v1(12.677,16.086)
  Top-Layer w0.3: v1(52.436,18.586) U200.12@52.436,20.066 v1(52.436,21.675)
  other v1: 4.065,0.6 6.605,0.6 9.145,0.6 11.685,0.6 14.795,0.6 18.095,0.6 18.925,0.6 21.675,0.6 24.13,0.6 26.67,0.6 29.21,0.6 31.75,0.6 34.29,0.6 36.83,0.6 39.475,0.6 41.95,0.6 44.625,0.6 47.15,0.6 49.525,0.6 54.6,0.65 56.95,0.645 1.525,1.1 16.46,1.775 56.95,1.915 0.729,2.8 56.95,3.185 56.95,6.995 0.729,7.366 56.95,8.265 39.731,9.445 56.95,9.535 0.729,10.16 56.95,10.805 38.275,10.825 2.925,11.115 14.725,11.098 6.25,11.396 0.729,11.43 56.95,12.075 0.729,12.7 56.95,13.345 0.729,13.97 56.95,14.615 0.729,15.24 56.95,15.885 35.45,15.9 56.95,17.155 0.729,18.034 56.95,18.425 56.95,19.695 56.95,20.965 14.273,21.216 15.15,21.923 56.95,22.235 0.729,22.612 56.95,23.505 16.46,23.637 1.525,24.312 56.95,24.775 3.315,24.812 6.605,24.812 9.145,24.812 11.685,24.812 14.795,24.812 18.095,24.812 18.925,24.812 21.615,24.812 24.13,24.812 26.67,24.812 29.21,24.812 31.75,24.812 34.29,24.812 36.83,24.812 39.87,24.807 41.768,24.812 45.229,24.812 48.825,24.812 52.4,24.812
  other v2: 46.678,11.951 47.911,11.951 49.144,11.951 46.678,13.184 47.911,13.184 49.144,13.184 46.678,14.417 47.911,14.417 49.144,14.417
ID_SYS: U100.22
NetC102_2: C102.2 U102.11 | length 1.5
  Top-Layer w0.2: U102.11@15.773,20.241 16.398,20.241 C102.2@16.998,20.841
NetC204_2: C204.2 L200.1 U201.18 | length 2.6
  Top-Layer w0.2: L200.1@27.085,14.748 27.31,14.523 C204.2@28.285,14.523 28.858,13.95 U201.18@29.36,13.95
NetD100_1: D100.1 R101.2 | length 18.5
  Top-Layer w0.15: D100.1@5.2,23.402 v1(6.023,23.402) ; R101.2@14.754,13.189 14.765,13.201 v1(15.48,13.201)
  Bottom Layer w0.15: v1(6.023,23.402) 10.828,23.402 12.85,21.38 12.85,16.975 14.964,14.861 14.964,13.717 v1(15.48,13.201)
NetD101_1: D101.1 R102.2 | length 18.2
  Top-Layer w0.15: D101.1@5.2,24.402 v1(6.025,24.402) ; R102.2@14.754,14.191 v1(15.48,14.191)
  Bottom Layer w0.15: v1(6.025,24.402) 6.725,23.702 10.952,23.702 13.15,21.504 13.15,17.099 15.48,14.769 v1(15.48,14.191)
NetD102_1: D102.1 R106.1 | length 1.4
  Top-Layer w0.15: R106.1@6.15,6.92 6.15,6.95 D102.1@7.15,7.95
NetR100_2: R100.2 U102.9 | length 6.9
  Top-Layer w0.15: R100.2@13.775,23.175 v1(14.575,23.175)
  Top-Layer w0.2: v1(16.473,19.266) 15.798,19.266 U102.9@15.773,19.241 v1@16.498,19.241
  Bottom Layer w0.15: v1(14.575,23.175) 16.473,21.277 v1(16.473,19.266)
NetR101_1: R101.1 U101.7 | length 1.3
  Top-Layer w0.25: U101.7@12.677,13.639 13.304,13.639 R101.1@13.754,13.189
NetR102_1: R102.1 U101.8 | length 1.1
  Top-Layer w0.25: U101.8@12.677,14.139 13.702,14.139 R102.1@13.754,14.191
NetR103_1: R103.1 U101.5 | length 2.1
  Top-Layer w0.2: U101.5@11.712,12.174 13.728,12.174 R103.1@13.754,12.2
NetR104_1: R104.1 U101.13 | length 4
  Top-Layer w0.15: U101.13@10.712,16.104 10.712,16.937 10.916,17.141 R104.1@13.754,17.141
NetR105_1: R105.1 U101.12 | length 3.3
  Top-Layer w0.15: U101.12@11.212,16.104 11.212,16.645 11.276,16.709 13.184,16.709 R105.1@13.754,16.139
NetTP200_1: TP200.1 U200.3 | length 13.1
  Top-Layer w0.15: U200.3@46.34,5.334 v1(46.34,6.653)
  Bottom Layer w0.15: v1(46.34,6.653) 49.018,3.975 53.175,3.975 TP200.1@55.88,1.27
NetTP201_1: TP201.1 U200.2 | length 11.6
  Top-Layer w0.15: U200.2@45.324,5.334 v1(45.324,6.653)
  Bottom Layer w0.15: v1(45.324,6.653) 48.402,3.575 51.035,3.575 TP201.1@53.34,1.27
NetTP202_1: TP202.1 U200.1 | length 10
  Top-Layer w0.15: U200.1@44.308,5.334 v1(44.308,6.653)
  Bottom Layer w0.15: v1(44.308,6.653) 47.936,3.025 49.045,3.025 TP202.1@50.8,1.27
NetTP203_1: TP203.1 U200.21 | length 17
  Top-Layer w0.2: U200.21@41.641,15.113 43.387,15.113 v1(43.75,14.75)
  Bottom Layer w0.15: TP203.1@40.64,1.27 42.2,2.83 42.2,13.2 v1(43.75,14.75)
NetTP204_1: TP204.1 U200.25 | length 12
  Top-Layer w0.2: U200.25@41.641,11.049 v1@43.272,11.049
  Bottom Layer w0.15: TP204.1@43.18,1.27 42.5,1.95 42.5,10.271 v1(43.275,11.046)
NetTP205_1: TP205.1 U200.26 | length 11.8
  Top-Layer w0.2: U200.26@41.641,10.033 v1@43.272,10.033
  Bottom Layer w0.15: v1(43.275,10.03) 42.8,9.555 42.8,4.19 TP205.1@45.72,1.27
NetTP206_1: TP206.1 U200.27 | length 11.4
  Top-Layer w0.2: U200.27@41.641,9.017 v1@43.272,9.017
  Bottom Layer w0.15: v1(43.275,9.014) 43.275,6.255 TP206.1@48.26,1.27
NetU102_3: U102.3 U102.4 U102.5 U102.6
